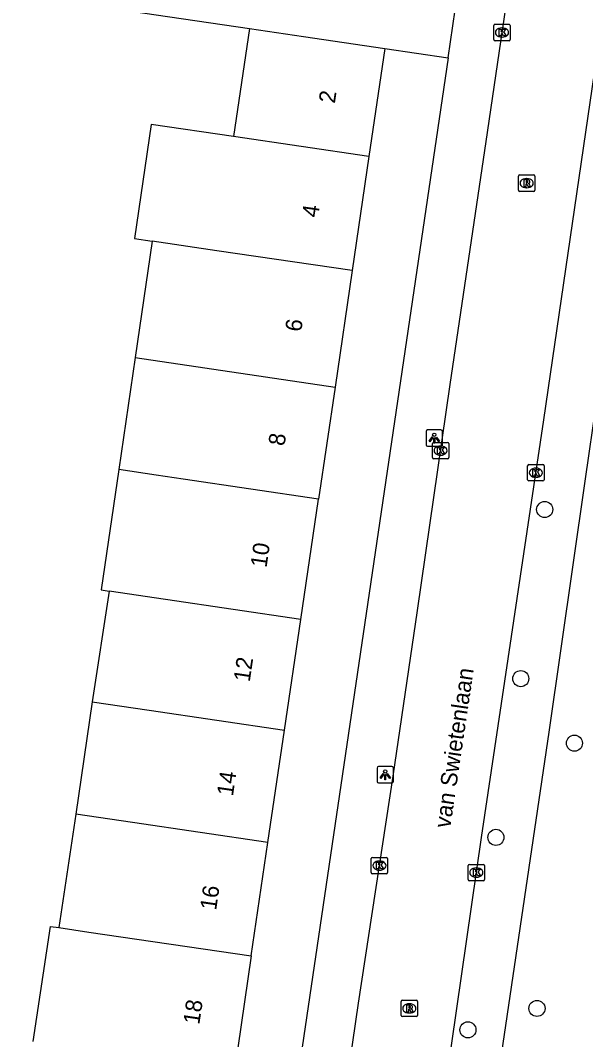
# Model space of a CAD drawing. Extents: x 161486 to 162249, y 379484 to 380829.
# Drawn here: x 162137.6 to 162172, y 380409.6 to 380471.6 of the extents above; entities that cross this region are included whole.
import ezdxf

# ---------------------------------------------------------------- set-up
doc = ezdxf.new("R2010")
doc.units = 0
for name, color, linetype in [('IMGEO_Boom', 7, 'Continuous'), ('IMGEO_Kolk', 7, 'Continuous'), ('IMGEO_Lichtpunt', 7, 'Continuous'), ('IMGEO_Openbare_ruimte_label', 7, 'Continuous'), ('IMGEO_Pand', 7, 'Continuous'), ('IMGEO_Pand_nummerreeks', 7, 'Continuous'), ('IMGEO_Rijbaan_lokaal_open', 7, 'Continuous'), ('IMGEO_Rioolput', 7, 'Continuous'), ('IMGEO_Voetpad_open', 7, 'Continuous')]:
    doc.layers.add(name, color=color, linetype=linetype)

msp = doc.modelspace()

# ---------------------------------------------------------------- linework, layer by layer
at = {"layer": 'IMGEO_Boom'}
for centre in [(162169.513, 380441.815), (162168.058, 380431.524), (162171.323, 380427.598), (162166.542, 380421.868), (162169.043, 380411.458), (162164.84, 380410.156)]:
    msp.add_circle(centre, 0.489, dxfattribs=at)
at = {"layer": 'IMGEO_Kolk'}
for p, q in [((162166.413, 380470.412), (162166.413, 380471.264)), ((162166.488, 380471.338), (162167.34, 380471.338)), ((162166.901, 380471.118), (162166.926, 380471.118)), ((162167.414, 380471.264), (162167.414, 380470.412)), ((162167.34, 380470.338), (162166.488, 380470.338)), ((162166.924, 380470.558), (162166.899, 380470.558)), ((162162.675, 380444.972), (162162.675, 380445.824)), ((162162.75, 380445.898), (162163.602, 380445.898)), ((162163.163, 380445.678), (162163.188, 380445.678)), ((162163.676, 380445.824), (162163.676, 380444.972)), ((162163.602, 380444.898), (162162.75, 380444.898)), ((162163.186, 380445.118), (162163.161, 380445.118)), ((162168.475, 380443.628), (162168.475, 380444.48)), ((162168.55, 380444.554), (162169.402, 380444.554)), ((162168.963, 380444.334), (162168.988, 380444.334)), ((162169.476, 380444.48), (162169.476, 380443.628)), ((162169.402, 380443.554), (162168.55, 380443.554)), ((162168.986, 380443.774), (162168.961, 380443.774)), ((162158.952, 380419.723), (162158.952, 380420.575)), ((162159.027, 380420.649), (162159.879, 380420.649)), ((162159.953, 380420.575), (162159.953, 380419.723)), ((162159.44, 380420.429), (162159.465, 380420.429)), ((162164.852, 380419.299), (162164.852, 380420.151)), ((162164.927, 380420.225), (162165.779, 380420.225)), ((162165.34, 380420.005), (162165.365, 380420.005)), ((162165.853, 380420.151), (162165.853, 380419.299)), ((162159.879, 380419.649), (162159.027, 380419.649)), ((162159.463, 380419.869), (162159.438, 380419.869)), ((162165.363, 380419.445), (162165.338, 380419.445)), ((162165.779, 380419.225), (162164.927, 380419.225))]:
    msp.add_line(p, q, dxfattribs=at)
for points in [[(162166.413, 380470.412), (162166.413, 380471.264)], [(162166.488, 380471.338), (162167.34, 380471.338)], [(162166.734, 380471.038), (162166.857, 380471.038), (162166.857, 380470.887), (162166.987, 380471.038), (162167.151, 380471.038), (162167.005, 380470.887), (162167.158, 380470.638), (162167.006, 380470.638), (162166.921, 380470.802), (162166.857, 380470.735), (162166.857, 380470.638), (162166.734, 380470.638), (162166.734, 380471.038)], [(162167.414, 380471.264), (162167.414, 380470.412)], [(162167.34, 380470.338), (162166.488, 380470.338)], [(162162.675, 380444.972), (162162.675, 380445.824)], [(162162.75, 380445.898), (162163.602, 380445.898)], [(162162.996, 380445.598), (162163.119, 380445.598), (162163.119, 380445.447), (162163.249, 380445.598), (162163.413, 380445.598), (162163.267, 380445.447), (162163.42, 380445.198), (162163.268, 380445.198), (162163.183, 380445.362), (162163.119, 380445.295), (162163.119, 380445.198), (162162.996, 380445.198), (162162.996, 380445.598)], [(162163.676, 380445.824), (162163.676, 380444.972)], [(162163.602, 380444.898), (162162.75, 380444.898)], [(162168.475, 380443.628), (162168.475, 380444.48)], [(162168.55, 380444.554), (162169.402, 380444.554)], [(162168.796, 380444.254), (162168.919, 380444.254), (162168.919, 380444.103), (162169.049, 380444.254), (162169.213, 380444.254), (162169.067, 380444.103), (162169.22, 380443.854), (162169.068, 380443.854), (162168.983, 380444.018), (162168.919, 380443.951), (162168.919, 380443.854), (162168.796, 380443.854), (162168.796, 380444.254)], [(162169.476, 380444.48), (162169.476, 380443.628)], [(162169.402, 380443.554), (162168.55, 380443.554)], [(162158.952, 380419.723), (162158.952, 380420.575)], [(162159.027, 380420.649), (162159.879, 380420.649)], [(162159.953, 380420.575), (162159.953, 380419.723)], [(162159.273, 380420.349), (162159.396, 380420.349), (162159.396, 380420.198), (162159.526, 380420.349), (162159.69, 380420.349), (162159.544, 380420.198), (162159.697, 380419.949), (162159.545, 380419.949), (162159.46, 380420.113), (162159.396, 380420.046), (162159.396, 380419.949), (162159.273, 380419.949), (162159.273, 380420.349)], [(162164.852, 380419.299), (162164.852, 380420.151)], [(162164.927, 380420.225), (162165.779, 380420.225)], [(162165.173, 380419.925), (162165.296, 380419.925), (162165.296, 380419.774), (162165.426, 380419.925), (162165.59, 380419.925), (162165.444, 380419.774), (162165.597, 380419.525), (162165.445, 380419.525), (162165.36, 380419.689), (162165.296, 380419.622), (162165.296, 380419.525), (162165.173, 380419.525), (162165.173, 380419.925)], [(162165.853, 380420.151), (162165.853, 380419.299)], [(162159.879, 380419.649), (162159.027, 380419.649)], [(162165.779, 380419.225), (162164.927, 380419.225)]]:
    msp.add_lwpolyline(points, dxfattribs=at)
for centre, start, end in [((162166.49, 380471.262), 91.55205, 178.44795), ((162166.49, 380471.262), 91.55205, 178.44795), ((162167.338, 380471.262), 1.55205, 88.44795), ((162167.338, 380471.262), 1.55205, 88.44795), ((162166.49, 380470.414), 181.55205, 268.44795), ((162166.49, 380470.414), 181.55205, 268.44795), ((162167.338, 380470.414), 271.55205, 358.44795), ((162167.338, 380470.414), 271.55205, 358.44795), ((162162.752, 380445.822), 91.55205, 178.44795), ((162162.752, 380445.822), 91.55205, 178.44795), ((162163.6, 380445.822), 1.55205, 88.44795), ((162163.6, 380445.822), 1.55205, 88.44795), ((162162.752, 380444.974), 181.55205, 268.44795), ((162162.752, 380444.974), 181.55205, 268.44795), ((162163.6, 380444.974), 271.55205, 358.44795), ((162163.6, 380444.974), 271.55205, 358.44795), ((162168.552, 380444.478), 91.55205, 178.44795), ((162168.552, 380444.478), 91.55205, 178.44795), ((162169.4, 380444.478), 1.55205, 88.44795), ((162169.4, 380444.478), 1.55205, 88.44795), ((162168.552, 380443.63), 181.55205, 268.44795), ((162168.552, 380443.63), 181.55205, 268.44795), ((162169.4, 380443.63), 271.55205, 358.44795), ((162169.4, 380443.63), 271.55205, 358.44795), ((162159.029, 380420.573), 91.55205, 178.44795), ((162159.029, 380420.573), 91.55205, 178.44795), ((162159.877, 380420.573), 1.55205, 88.44795), ((162159.877, 380420.573), 1.55205, 88.44795), ((162164.929, 380420.149), 91.55205, 178.44795), ((162164.929, 380420.149), 91.55205, 178.44795), ((162165.777, 380420.149), 1.55205, 88.44795), ((162165.777, 380420.149), 1.55205, 88.44795), ((162159.029, 380419.725), 181.55205, 268.44795), ((162159.029, 380419.725), 181.55205, 268.44795), ((162159.877, 380419.725), 271.55205, 358.44795), ((162159.877, 380419.725), 271.55205, 358.44795), ((162164.929, 380419.301), 181.55205, 268.44795), ((162164.929, 380419.301), 181.55205, 268.44795), ((162165.777, 380419.301), 271.55205, 358.44795), ((162165.777, 380419.301), 271.55205, 358.44795)]:
    msp.add_arc(centre, 0.0765, start, end, dxfattribs=at)
for centre, major_axis, ratio, start_param, end_param in [((162166.9, 380470.838), (-0.387, 0.002), 0.722429, 4.712389, 7.853982), ((162166.925, 380470.838), (-0.39, 0.002), 0.717154, 1.570796, 4.712389), ((162163.162, 380445.398), (-0.387, 0.002), 0.722429, 4.712389, 7.853982), ((162163.187, 380445.398), (-0.39, 0.002), 0.717154, 1.570796, 4.712389), ((162168.962, 380444.054), (-0.387, 0.002), 0.722429, 4.712389, 7.853982), ((162168.987, 380444.054), (-0.39, 0.002), 0.717154, 1.570796, 4.712389), ((162159.439, 380420.149), (-0.387, 0.002), 0.722429, 4.712389, 7.853982), ((162159.464, 380420.149), (-0.39, 0.002), 0.717154, 1.570796, 4.712389), ((162165.339, 380419.725), (-0.387, 0.002), 0.722429, 4.712389, 7.853982), ((162165.364, 380419.725), (-0.39, 0.002), 0.717154, 1.570796, 4.712389)]:
    msp.add_ellipse(centre, major_axis=major_axis, ratio=ratio, start_param=start_param, end_param=end_param, dxfattribs=at)
at = {"layer": 'IMGEO_Lichtpunt'}
for p, q in [((162162.293, 380446.564), (162162.293, 380445.757)), ((162162.293, 380446.564), (162162.293, 380445.757)), ((162163.195, 380446.659), (162162.387, 380446.659)), ((162163.195, 380446.659), (162162.387, 380446.659)), ((162163.289, 380445.757), (162163.289, 380446.564)), ((162163.289, 380445.757), (162163.289, 380446.564)), ((162162.387, 380445.663), (162163.195, 380445.663)), ((162162.387, 380445.663), (162163.195, 380445.663)), ((162160.209, 380426.179), (162159.401, 380426.179)), ((162160.209, 380426.179), (162159.401, 380426.179)), ((162159.307, 380426.084), (162159.307, 380425.277)), ((162159.307, 380426.084), (162159.307, 380425.277)), ((162160.303, 380425.277), (162160.303, 380426.084)), ((162160.303, 380425.277), (162160.303, 380426.084)), ((162159.401, 380425.183), (162160.209, 380425.183)), ((162159.401, 380425.183), (162160.209, 380425.183))]:
    msp.add_line(p, q, dxfattribs=at)
for points in [[(162162.667, 380446.228), (162162.706, 380446.2), (162162.518, 380445.938), (162162.48, 380445.965), (162162.667, 380446.228)], [(162162.769, 380446.18), (162162.816, 380446.18), (162162.816, 380445.858), (162162.769, 380445.858), (162162.769, 380446.18)], [(162162.879, 380446.2), (162162.917, 380446.227), (162163.104, 380445.965), (162163.065, 380445.937), (162162.879, 380446.2)], [(162159.681, 380425.748), (162159.72, 380425.72), (162159.532, 380425.458), (162159.494, 380425.485), (162159.681, 380425.748)], [(162159.783, 380425.7), (162159.83, 380425.7), (162159.83, 380425.378), (162159.783, 380425.378), (162159.783, 380425.7)], [(162159.893, 380425.72), (162159.931, 380425.747), (162160.118, 380425.485), (162160.079, 380425.457), (162159.893, 380425.72)]]:
    msp.add_lwpolyline(points, dxfattribs=at)
for centre in [(162162.792, 380446.362), (162159.806, 380425.882)]:
    msp.add_circle(centre, 0.0994, dxfattribs=at)
for centre, start, end in [((162162.387, 380446.564), 90, 180), ((162162.387, 380446.564), 90, 180), ((162163.195, 380446.564), 0, 90), ((162163.195, 380446.564), 0, 90), ((162162.387, 380445.757), 180, 270), ((162162.387, 380445.757), 180, 270), ((162163.195, 380445.757), 270, 0), ((162163.195, 380445.757), 270, 360), ((162159.401, 380426.084), 90, 180), ((162159.401, 380426.084), 90, 180), ((162160.209, 380426.084), 0, 90), ((162160.209, 380426.084), 0, 90), ((162159.401, 380425.277), 180, 270), ((162159.401, 380425.277), 180, 270), ((162160.209, 380425.277), 270, 0), ((162160.209, 380425.277), 270, 360)]:
    msp.add_arc(centre, 0.0946, start, end, dxfattribs=at)
at = {"layer": 'IMGEO_Pand'}
for points in [[(162151.539, 380471.087), (162150.572, 380464.515)], [(162151.539, 380471.087), (162154.835, 380470.602), (162159.781, 380469.874)], [(162159.781, 380469.874), (162158.814, 380463.303)], [(162150.572, 380464.515), (162145.56, 380465.252), (162144.537, 380458.299), (162145.628, 380458.139)], [(162158.814, 380463.303), (162150.572, 380464.515)], [(162158.814, 380463.303), (162157.791, 380456.35)], [(162145.628, 380458.139), (162144.587, 380451.063)], [(162157.791, 380456.35), (162149.549, 380457.562), (162145.628, 380458.139)], [(162157.791, 380456.35), (162156.748, 380449.266)], [(162144.587, 380451.063), (162143.584, 380444.243)], [(162144.587, 380451.063), (162156.748, 380449.266)], [(162156.748, 380449.266), (162155.745, 380442.453)], [(162143.584, 380444.243), (162142.507, 380436.927), (162142.991, 380436.856)], [(162155.745, 380442.453), (162147.503, 380443.666), (162145.87, 380443.906), (162143.584, 380444.243)], [(162154.667, 380435.13), (162155.745, 380442.453)], [(162142.991, 380436.856), (162141.972, 380430.121)], [(162154.667, 380435.13), (162146.426, 380436.348), (162142.991, 380436.856)], [(162153.677, 380428.398), (162154.667, 380435.13)], [(162141.972, 380430.121), (162140.964, 380423.274)], [(162141.972, 380430.121), (162145.435, 380429.611), (162153.677, 380428.398)], [(162152.669, 380421.553), (162153.677, 380428.398)], [(162140.964, 380423.274), (162139.928, 380416.376)], [(162152.669, 380421.553), (162144.427, 380422.765), (162140.964, 380423.274)], [(162151.653, 380414.652), (162152.669, 380421.553)], [(162138.383, 380409.457), (162139.434, 380416.449), (162139.928, 380416.376)], [(162139.928, 380416.376), (162141.772, 380416.105), (162151.653, 380414.652)], [(162151.653, 380414.652), (162150.624, 380407.656)]]:
    msp.add_lwpolyline(points, dxfattribs=at)
at = {"layer": 'IMGEO_Rijbaan_lokaal_open'}
for points in [[(162151.169, 380368.675), (162151.181, 380368.685), (162151.649, 380369.213), (162151.93, 380369.933), (162152.195, 380371.415), (162153.167, 380377.743), (162154.01, 380383.532), (162155.022, 380390.21), (162156.042, 380397.149), (162156.439, 380400.028), (162156.597, 380400.888), (162158.184, 380411.77), (162160.279, 380425.584), (162161.774, 380435.673), (162163.758, 380449.417), (162165.94, 380464.212), (162167.444, 380474.43), (162168.866, 380483.92), (162170.091, 380492.47), (162170.946, 380498.488), (162171.148, 380500), (162171.2, 380500.387)], [(162157.964, 380369.561), (162158.063, 380370.18), (162158.499, 380373.03), (162158.866, 380375.759), (162159.392, 380379.098), (162160.224, 380384.497), (162160.918, 380389.167), (162161.642, 380394.265), (162162.525, 380400.034), (162162.65, 380400.918), (162165.657, 380421.852), (162169.455, 380447.274), (162172.695, 380469.351), (162175.822, 380490.401), (162176.923, 380497.863), (162177.161, 380499.459), (162177.223, 380500)]]:
    msp.add_lwpolyline(points, dxfattribs=at)
at = {"layer": 'IMGEO_Rioolput'}
for p, q in [((162167.915, 380461.245), (162167.915, 380462.097)), ((162167.99, 380462.171), (162168.842, 380462.171)), ((162168.916, 380462.097), (162168.916, 380461.245)), ((162168.403, 380461.951), (162168.428, 380461.951)), ((162168.842, 380461.171), (162167.99, 380461.171)), ((162168.426, 380461.391), (162168.401, 380461.391)), ((162160.772, 380411.035), (162160.772, 380411.887)), ((162160.847, 380411.961), (162161.699, 380411.961)), ((162161.773, 380411.887), (162161.773, 380411.035)), ((162161.26, 380411.741), (162161.285, 380411.741)), ((162161.699, 380410.961), (162160.847, 380410.961)), ((162161.283, 380411.181), (162161.258, 380411.181))]:
    msp.add_line(p, q, dxfattribs=at)
for points in [[(162167.915, 380461.245), (162167.915, 380462.097)], [(162167.99, 380462.171), (162168.842, 380462.171)], [(162168.916, 380462.097), (162168.916, 380461.245)], [(162168.504, 380461.869), (162168.252, 380461.871), (162168.252, 380461.471)], [(162168.252, 380461.471), (162168.376, 380461.471), (162168.376, 380461.633), (162168.387, 380461.633)], [(162168.43, 380461.79), (162168.376, 380461.79), (162168.376, 380461.709)], [(162168.376, 380461.709), (162168.428, 380461.709)], [(162168.434, 380461.604), (162168.505, 380461.471), (162168.645, 380461.471), (162168.58, 380461.597)], [(162168.842, 380461.171), (162167.99, 380461.171)], [(162160.772, 380411.035), (162160.772, 380411.887)], [(162160.847, 380411.961), (162161.699, 380411.961)], [(162161.773, 380411.887), (162161.773, 380411.035)], [(162161.361, 380411.659), (162161.109, 380411.661), (162161.109, 380411.261)], [(162161.109, 380411.261), (162161.233, 380411.261), (162161.233, 380411.423), (162161.244, 380411.423)], [(162161.287, 380411.58), (162161.233, 380411.58), (162161.233, 380411.499)], [(162161.233, 380411.499), (162161.285, 380411.499)], [(162161.291, 380411.394), (162161.362, 380411.261), (162161.502, 380411.261), (162161.437, 380411.387)], [(162161.699, 380410.961), (162160.847, 380410.961)]]:
    msp.add_lwpolyline(points, dxfattribs=at)
for centre, radius, start, end in [((162167.992, 380462.095), 0.0765, 91.55205, 178.44795), ((162167.992, 380462.095), 0.0765, 91.55205, 178.44795), ((162168.84, 380462.095), 0.0765, 1.55205, 88.44795), ((162168.84, 380462.095), 0.0765, 1.55205, 88.44795), ((162168.386, 380461.58), 0.0533, 26.02933, 88.69889), ((162168.412, 380461.898), 0.19, 274.7715, 282.96867), ((162168.436, 380461.694), 0.0964, 77.00612, 93.18647), ((162168.45, 380461.751), 0.0378, 276.66336, 79.67722), ((162168.503, 380461.759), 0.109, 350.36119, 89.41601), ((162168.501, 380461.759), 0.112, 277.58423, 350.98172), ((162168.485, 380461.544), 0.108, 29.51342, 73.79051), ((162167.992, 380461.247), 0.0765, 181.55205, 268.44795), ((162167.992, 380461.247), 0.0765, 181.55205, 268.44795), ((162168.84, 380461.247), 0.0765, 271.55205, 358.44795), ((162168.84, 380461.247), 0.0765, 271.55205, 358.44795), ((162160.849, 380411.885), 0.0765, 91.55205, 178.44795), ((162160.849, 380411.885), 0.0765, 91.55205, 178.44795), ((162161.697, 380411.885), 0.0765, 1.55205, 88.44795), ((162161.697, 380411.885), 0.0765, 1.55205, 88.44795), ((162161.243, 380411.37), 0.0533, 26.02933, 88.69889), ((162161.269, 380411.688), 0.19, 274.7715, 282.96867), ((162161.293, 380411.484), 0.0964, 77.00612, 93.18647), ((162161.307, 380411.541), 0.0378, 276.66336, 79.67722), ((162161.36, 380411.549), 0.109, 350.36119, 89.41601), ((162161.358, 380411.549), 0.112, 277.58423, 350.98172), ((162161.342, 380411.334), 0.108, 29.51342, 73.79051), ((162160.849, 380411.037), 0.0765, 181.55205, 268.44795), ((162160.849, 380411.037), 0.0765, 181.55205, 268.44795), ((162161.697, 380411.037), 0.0765, 271.55205, 358.44795), ((162161.697, 380411.037), 0.0765, 271.55205, 358.44795)]:
    msp.add_arc(centre, radius, start, end, dxfattribs=at)
for centre, major_axis, ratio, start_param, end_param in [((162168.402, 380461.671), (-0.387, 0.002), 0.722429, 4.712389, 7.853982), ((162168.427, 380461.671), (-0.39, 0.002), 0.717154, 1.570796, 4.712389), ((162161.259, 380411.461), (-0.387, 0.002), 0.722429, 4.712389, 7.853982), ((162161.284, 380411.461), (-0.39, 0.002), 0.717154, 1.570796, 4.712389)]:
    msp.add_ellipse(centre, major_axis=major_axis, ratio=ratio, start_param=start_param, end_param=end_param, dxfattribs=at)
at = {"layer": 'IMGEO_Voetpad_open'}
for points in [[(162133.908, 380470.008), (162134.481, 380473.597), (162151.539, 380471.087)], [(162163.629, 380469.306), (162164.059, 380472.218)], [(162159.781, 380469.874), (162163.629, 380469.306)], [(162163.629, 380469.306), (162153.198, 380398.656)], [(162161.455, 380369.692), (162161.191, 380370.053), (162169.786, 380428.27), (162171.968, 380443.55), (162172.687, 380448.441)]]:
    msp.add_lwpolyline(points, dxfattribs=at)

# ---------------------------------------------------------------- texts
at = {"layer": 'IMGEO_Openbare_ruimte_label'}
msp.add_text('van Swietenlaan', height=1, rotation=81.54574, dxfattribs=at).set_placement((162163.759, 380422.395))
at = {"layer": 'IMGEO_Pand_nummerreeks'}
for s, rotation, p in [('2', 81.6273, (162156.737, 380466.492)), ('4', 81.6293, (162155.713, 380459.544)), ('6', 81.6293, (162154.69, 380452.595)), ('8', 81.6293, (162153.668, 380445.65)), ('10', 81.6293, (162152.578, 380438.244)), ('12', 81.6293, (162151.555, 380431.289)), ('14', 81.6273, (162150.533, 380424.343)), ('16', 81.6273, (162149.51, 380417.394)), ('18', 81.6293, (162148.487, 380410.447))]:
    msp.add_text(s, height=1, rotation=rotation, dxfattribs=at).set_placement(p)

doc.saveas('drawing.dxf')
